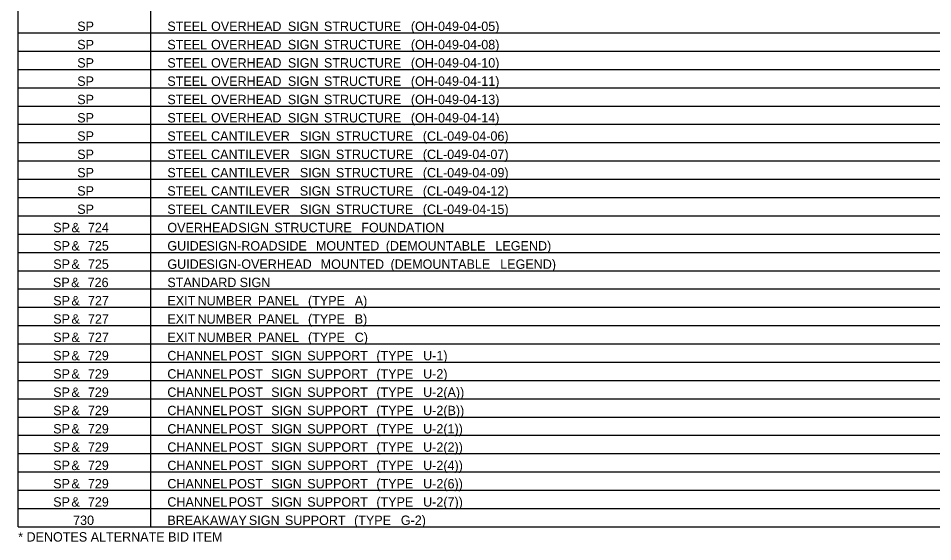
# Model space of a CAD drawing. Extents: x 1226603 to 1228117, y 151305 to 152343.
# Drawn here: x 1227295.3 to 1227709.6, y 151323.9 to 151561 of the extents above; entities that cross this region are included whole.
import ezdxf

# ---------------------------------------------------------------- set-up
doc = ezdxf.new("R2010")
doc.units = 0
doc.layers.add('R_Dimension', color=7, linetype='Continuous')

msp = doc.modelspace()

# ---------------------------------------------------------------- linework, layer by layer
at = {"layer": 'R_Dimension'}
for p, q in [((1227295.33, 151330.69), (1227295.33, 152231.95)), ((1227355.42, 151330.69), (1227355.42, 152231.95)), ((1227295.33, 151554.45), (1227925.18, 151554.45)), ((1227295.33, 151546.16), (1227925.18, 151546.16)), ((1227295.33, 151537.88), (1227925.18, 151537.88)), ((1227295.33, 151529.59), (1227925.18, 151529.59)), ((1227295.33, 151521.3), (1227925.18, 151521.3)), ((1227295.33, 151513.01), (1227925.18, 151513.01)), ((1227295.33, 151504.73), (1227925.18, 151504.73)), ((1227295.33, 151496.44), (1227925.18, 151496.44)), ((1227295.33, 151488.15), (1227925.18, 151488.15)), ((1227295.33, 151479.86), (1227925.18, 151479.86)), ((1227295.33, 151471.58), (1227925.18, 151471.58)), ((1227295.33, 151463.29), (1227925.18, 151463.29)), ((1227295.33, 151455), (1227925.18, 151455)), ((1227295.33, 151446.71), (1227925.18, 151446.71)), ((1227295.33, 151438.43), (1227925.18, 151438.43)), ((1227295.33, 151430.14), (1227925.18, 151430.14)), ((1227295.33, 151421.85), (1227925.18, 151421.85)), ((1227295.33, 151413.56), (1227925.18, 151413.56)), ((1227295.33, 151405.28), (1227925.18, 151405.28)), ((1227295.33, 151396.99), (1227925.18, 151396.99)), ((1227295.33, 151388.7), (1227925.18, 151388.7)), ((1227295.33, 151380.41), (1227925.18, 151380.41)), ((1227295.33, 151372.13), (1227925.18, 151372.13)), ((1227295.33, 151363.84), (1227925.18, 151363.84)), ((1227295.33, 151355.55), (1227925.18, 151355.55)), ((1227295.33, 151347.26), (1227925.18, 151347.26)), ((1227295.33, 151338.98), (1227925.18, 151338.98)), ((1227295.33, 151330.69), (1227925.18, 151330.69))]:
    msp.add_line(p, q, dxfattribs=at)

# ---------------------------------------------------------------- texts
for s, height, p in [('SP', 4.25, (1227322.04, 151555.3)), ('STEEL', 4.25, (1227362.87, 151555.3)), (' OVERHEAD', 4.25, (1227381.08, 151555.3)), (' SIGN', 4.25, (1227415.88, 151555.3)), (' STRUCTURE', 4.25, (1227432.21, 151555.3)), (' (OH-049-04-05)', 4.25, (1227471.6, 151555.3)), ('SP', 4.25, (1227322.04, 151547.01)), ('STEEL', 4.25, (1227362.87, 151547.01)), (' OVERHEAD', 4.25, (1227381.08, 151547.01)), (' SIGN', 4.25, (1227415.88, 151547.01)), (' STRUCTURE', 4.25, (1227432.21, 151547.01)), (' (OH-049-04-08)', 4.25, (1227471.6, 151547.01)), ('SP', 4.25, (1227322.04, 151538.73)), ('STEEL', 4.25, (1227362.87, 151538.73)), (' OVERHEAD', 4.25, (1227381.08, 151538.73)), (' SIGN', 4.25, (1227415.88, 151538.73)), (' STRUCTURE', 4.25, (1227432.21, 151538.73)), (' (OH-049-04-10)', 4.25, (1227471.6, 151538.73)), ('SP', 4.25, (1227322.04, 151530.44)), ('STEEL', 4.25, (1227362.87, 151530.44)), (' OVERHEAD', 4.25, (1227381.08, 151530.44)), (' SIGN', 4.25, (1227415.88, 151530.44)), (' STRUCTURE', 4.25, (1227432.21, 151530.44)), (' (OH-049-04-11)', 4.25, (1227471.6, 151530.44)), ('SP', 4.25, (1227322.04, 151522.15)), ('STEEL', 4.25, (1227362.87, 151522.15)), (' OVERHEAD', 4.25, (1227381.08, 151522.15)), (' SIGN', 4.25, (1227415.88, 151522.15)), (' STRUCTURE', 4.25, (1227432.21, 151522.15)), (' (OH-049-04-13)', 4.25, (1227471.6, 151522.15)), ('SP', 4.25, (1227322.04, 151513.86)), ('STEEL', 4.25, (1227362.87, 151513.86)), (' OVERHEAD', 4.25, (1227381.08, 151513.86)), (' SIGN', 4.25, (1227415.88, 151513.86)), (' STRUCTURE', 4.25, (1227432.21, 151513.86)), (' (OH-049-04-14)', 4.25, (1227471.6, 151513.86)), ('SP', 4.25, (1227322.04, 151505.58)), ('STEEL', 4.25, (1227362.87, 151505.58)), (' CANTILEVER', 4.25, (1227381.08, 151505.58)), (' SIGN', 4.25, (1227421.3, 151505.58)), (' STRUCTURE', 4.25, (1227437.63, 151505.58)), (' (CL-049-04-06)', 4.25, (1227477.02, 151505.58)), ('SP', 4.25, (1227322.04, 151497.29)), ('STEEL', 4.25, (1227362.87, 151497.29)), (' CANTILEVER', 4.25, (1227381.08, 151497.29)), (' SIGN', 4.25, (1227421.3, 151497.29)), (' STRUCTURE', 4.25, (1227437.63, 151497.29)), (' (CL-049-04-07)', 4.25, (1227477.02, 151497.29)), ('SP', 4.25, (1227322.04, 151489)), ('STEEL', 4.25, (1227362.87, 151489)), (' CANTILEVER', 4.25, (1227381.08, 151489)), (' SIGN', 4.25, (1227421.3, 151489)), (' STRUCTURE', 4.25, (1227437.63, 151489)), (' (CL-049-04-09)', 4.25, (1227477.02, 151489)), ('SP', 4.25, (1227322.04, 151480.71)), ('STEEL', 4.25, (1227362.87, 151480.71)), (' CANTILEVER', 4.25, (1227381.08, 151480.71)), (' SIGN', 4.25, (1227421.3, 151480.71)), (' STRUCTURE', 4.25, (1227437.63, 151480.71)), (' (CL-049-04-12)', 4.25, (1227477.02, 151480.71)), ('SP', 4.25, (1227322.04, 151472.43)), ('STEEL', 4.25, (1227362.87, 151472.43)), (' CANTILEVER', 4.25, (1227381.08, 151472.43)), (' SIGN', 4.25, (1227421.3, 151472.43)), (' STRUCTURE', 4.25, (1227437.63, 151472.43)), (' (CL-049-04-15)', 4.25, (1227477.02, 151472.43)), ('SP', 4.25, (1227311.17, 151464.14)), (' &', 4.25, (1227317.83, 151464.14)), (' 724', 4.25, (1227325.29, 151464.14)), ('OVERHEAD', 4.25, (1227362.87, 151464.14)), (' SIGN', 4.25, (1227393.43, 151464.14)), (' STRUCTURE', 4.25, (1227409.76, 151464.14)), (' FOUNDATION', 4.25, (1227449.15, 151464.14)), ('SP', 4.25, (1227311.17, 151455.85)), (' &', 4.25, (1227317.83, 151455.85)), (' 725', 4.25, (1227325.29, 151455.85)), ('GUIDE', 4.25, (1227362.87, 151455.85)), (' SIGN-ROADSIDE', 4.25, (1227379, 151455.85)), (' MOUNTED', 4.25, (1227428.57, 151455.85)), (' (DEMOUNTABLE', 4.25, (1227460.22, 151455.85)), (' LEGEND)', 4.25, (1227509.92, 151455.85)), ('SP', 4.25, (1227311.17, 151447.56)), (' &', 4.25, (1227317.83, 151447.56)), (' 725', 4.25, (1227325.29, 151447.56)), ('GUIDE', 4.25, (1227362.87, 151447.56)), (' SIGN-OVERHEAD', 4.25, (1227379, 151447.56)), (' MOUNTED', 4.25, (1227430.74, 151447.56)), (' (DEMOUNTABLE', 4.25, (1227462.4, 151447.56)), (' LEGEND)', 4.25, (1227512.09, 151447.56)), ('SP', 4.25, (1227311.05, 151439.28)), (' &', 4.25, (1227317.71, 151439.28)), (' 726', 4.25, (1227325.17, 151439.28)), ('STANDARD', 4.25, (1227362.87, 151439.28)), (' SIGN', 4.25, (1227394.03, 151439.28)), ('SP', 4.25, (1227311.17, 151430.99)), (' &', 4.25, (1227317.83, 151430.99)), (' 727', 4.25, (1227325.29, 151430.99)), ('EXIT', 4.25, (1227362.87, 151430.99)), (' NUMBER', 4.25, (1227374.96, 151430.99)), (' PANEL', 4.25, (1227402.33, 151430.99)), (' (TYPE', 4.25, (1227424.99, 151430.99)), (' A)', 4.25, (1227446.17, 151430.99)), ('SP', 4.25, (1227311.17, 151422.7)), (' &', 4.25, (1227317.83, 151422.7)), (' 727', 4.25, (1227325.29, 151422.7)), ('EXIT', 4.25, (1227362.87, 151422.7)), (' NUMBER', 4.25, (1227374.96, 151422.7)), (' PANEL', 4.25, (1227402.33, 151422.7)), (' (TYPE', 4.25, (1227424.99, 151422.7)), (' B)', 4.25, (1227446.17, 151422.7)), ('SP', 4.25, (1227311.17, 151414.41)), (' &', 4.25, (1227317.83, 151414.41)), (' 727', 4.25, (1227325.29, 151414.41)), ('EXIT', 4.25, (1227362.87, 151414.41)), (' NUMBER', 4.25, (1227374.96, 151414.41)), (' PANEL', 4.25, (1227402.33, 151414.41)), (' (TYPE', 4.25, (1227424.99, 151414.41)), (' C)', 4.25, (1227446.17, 151414.41)), ('SP', 4.25, (1227311.15, 151406.13)), (' &', 4.25, (1227317.81, 151406.13)), (' 729', 4.25, (1227325.27, 151406.13)), ('CHANNEL', 4.25, (1227362.87, 151406.13)), (' POST', 4.25, (1227389.11, 151406.13)), (' SIGN', 4.25, (1227408.32, 151406.13)), (' SUPPORT', 4.25, (1227424.65, 151406.13)), (' (TYPE', 4.25, (1227455.97, 151406.13)), (' U-1)', 4.25, (1227477.16, 151406.13)), ('SP', 4.25, (1227311.15, 151397.84)), (' &', 4.25, (1227317.81, 151397.84)), (' 729', 4.25, (1227325.27, 151397.84)), ('CHANNEL', 4.25, (1227362.87, 151397.84)), (' POST', 4.25, (1227389.11, 151397.84)), (' SIGN', 4.25, (1227408.32, 151397.84)), (' SUPPORT', 4.25, (1227424.65, 151397.84)), (' (TYPE', 4.25, (1227455.97, 151397.84)), (' U-2)', 4.25, (1227477.16, 151397.84)), ('SP', 4.25, (1227311.15, 151389.55)), (' &', 4.25, (1227317.81, 151389.55)), (' 729', 4.25, (1227325.27, 151389.55)), ('CHANNEL', 4.25, (1227362.87, 151389.55)), (' POST', 4.25, (1227389.11, 151389.55)), (' SIGN', 4.25, (1227408.32, 151389.55)), (' SUPPORT', 4.25, (1227424.65, 151389.55)), (' (TYPE', 4.25, (1227455.97, 151389.55)), (' U-2(A))', 4.25, (1227477.16, 151389.55)), ('SP', 4.25, (1227311.15, 151381.26)), (' &', 4.25, (1227317.81, 151381.26)), (' 729', 4.25, (1227325.27, 151381.26)), ('CHANNEL', 4.25, (1227362.87, 151381.26)), (' POST', 4.25, (1227389.11, 151381.26)), (' SIGN', 4.25, (1227408.32, 151381.26)), (' SUPPORT', 4.25, (1227424.65, 151381.26)), (' (TYPE', 4.25, (1227455.97, 151381.26)), (' U-2(B))', 4.25, (1227477.16, 151381.26)), ('SP', 4.25, (1227311.15, 151372.98)), (' &', 4.25, (1227317.81, 151372.98)), (' 729', 4.25, (1227325.27, 151372.98)), ('CHANNEL', 4.25, (1227362.87, 151372.98)), (' POST', 4.25, (1227389.11, 151372.98)), (' SIGN', 4.25, (1227408.32, 151372.98)), (' SUPPORT', 4.25, (1227424.65, 151372.98)), (' (TYPE', 4.25, (1227455.97, 151372.98)), (' U-2(1))', 4.25, (1227477.16, 151372.98)), ('SP', 4.25, (1227311.15, 151364.69)), (' &', 4.25, (1227317.81, 151364.69)), (' 729', 4.25, (1227325.27, 151364.69)), ('CHANNEL', 4.25, (1227362.87, 151364.69)), (' POST', 4.25, (1227389.11, 151364.69)), (' SIGN', 4.25, (1227408.32, 151364.69)), (' SUPPORT', 4.25, (1227424.65, 151364.69)), (' (TYPE', 4.25, (1227455.97, 151364.69)), (' U-2(2))', 4.25, (1227477.16, 151364.69)), ('SP', 4.25, (1227311.15, 151356.4)), (' &', 4.25, (1227317.81, 151356.4)), (' 729', 4.25, (1227325.27, 151356.4)), ('CHANNEL', 4.25, (1227362.87, 151356.4)), (' POST', 4.25, (1227389.11, 151356.4)), (' SIGN', 4.25, (1227408.32, 151356.4)), (' SUPPORT', 4.25, (1227424.65, 151356.4)), (' (TYPE', 4.25, (1227455.97, 151356.4)), (' U-2(4))', 4.25, (1227477.16, 151356.4)), ('SP', 4.25, (1227311.15, 151348.11)), (' &', 4.25, (1227317.81, 151348.11)), (' 729', 4.25, (1227325.27, 151348.11)), ('CHANNEL', 4.25, (1227362.87, 151348.11)), (' POST', 4.25, (1227389.11, 151348.11)), (' SIGN', 4.25, (1227408.32, 151348.11)), (' SUPPORT', 4.25, (1227424.65, 151348.11)), (' (TYPE', 4.25, (1227455.97, 151348.11)), (' U-2(6))', 4.25, (1227477.16, 151348.11)), ('SP', 4.25, (1227311.15, 151339.83)), (' &', 4.25, (1227317.81, 151339.83)), (' 729', 4.25, (1227325.27, 151339.83)), ('CHANNEL', 4.25, (1227362.87, 151339.83)), (' POST', 4.25, (1227389.11, 151339.83)), (' SIGN', 4.25, (1227408.32, 151339.83)), (' SUPPORT', 4.25, (1227424.65, 151339.83)), (' (TYPE', 4.25, (1227455.97, 151339.83)), (' U-2(7))', 4.25, (1227477.16, 151339.83)), ('730', 4.25, (1227320.17, 151331.54)), ('BREAKAWAY', 4.25, (1227362.87, 151331.54)), (' SIGN', 4.25, (1227398.21, 151331.54)), (' SUPPORT', 4.25, (1227414.54, 151331.54)), (' (TYPE', 4.25, (1227445.87, 151331.54)), (' G-2)', 4.25, (1227467.05, 151331.54)), ('* DENOTES ALTERNATE BID ITEM', 4.2525, (1227295.27, 151324))]:
    msp.add_text(s, height=height, dxfattribs=at).set_placement(p)

doc.saveas('drawing.dxf')
